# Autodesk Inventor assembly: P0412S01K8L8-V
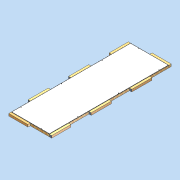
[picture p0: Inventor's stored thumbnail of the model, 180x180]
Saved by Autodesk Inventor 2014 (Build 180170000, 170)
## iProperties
Created: 2011-04
Part Number: P0412S01K8L8-V
Document SubType Name: Assembly
Designer: david.appleford
Description: 1w x 3w 01 Panel - 8 Locks 8 Lugs
Mass: 70000 g
Surface Area: 103979 cm^2
Volume: 351773 cm^3
Density: 0.198992 g/cm^3
Cost Center: £228.00
Justset: False
Title: 1w x 3w 01 Panel - 8 Locks 8 Lugs
Author: david.appleford
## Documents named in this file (4)
- C:\Documents and Settings\john.everitt\Local Settings\My Documents\Vault\Production MkII\VIRTUAL ELEMENTS\Virtual Walls\Virtual Timber + MgO\P0412S01K8L8-V.iam
- C:\Documents and Settings\john.everitt\Local Settings\My Documents\Vault\Production MkII\VIRTUAL ELEMENTS\Virtual Lugs\Superceded Lugs\LA02C3V.ipt
- C:\Documents and Settings\john.everitt\Local Settings\My Documents\Vault\Production MkII\VIRTUAL ELEMENTS\Virtual Lugs\Superceded Lugs\LA02M3V.ipt
- C:\Documents and Settings\john.everitt\Local Settings\My Documents\Vault\Production MkII\Virtual Elements\Virtual Walls\Virtual Timber + MgO\P0412S01K8-V.ipt
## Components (9 placed, 3 different names)
1. P0412S01K8-V:1 — Mate:1, Flush:1, Flush:2, Mate:2, Flush:3, Flush:4, Mate:3, Flush:5, Flush:6, Mate:4, Flush:7, Flush:8, Mate:5, Mate:6, Flush:9, Flush:10, Mate:7, Mate:8, Flush:11, Flush:12
2. LA02C3V:1 — Mate:1, Flush:1, Flush:2, Mate:9
3. LA02C3V:2 — Mate:2, Flush:3, Flush:4
4. LA02C3V:3 — Mate:4, Flush:7, Flush:8
5. LA02C3V:4 — Mate:3, Flush:5, Flush:6, Mate:11
6. LA02M3V:1 — Mate:6, Flush:9, Mate:11, Mate:12
7. LA02M3V:2 — Mate:5, Flush:10, Mate:12
8. LA02M3V:3 — Mate:8, Flush:12, Mate:10
9. LA02M3V:4 — Mate:7, Flush:11, Mate:9, Mate:10
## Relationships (24: Mate 12, Flush 12)
- Mate:1: P0412S01K8-V:1 ↔ LA02C3V:1
- Flush:1: P0412S01K8-V:1 ↔ LA02C3V:1
- Flush:2: P0412S01K8-V:1 ↔ LA02C3V:1
- Mate:2: P0412S01K8-V:1 ↔ LA02C3V:2
- Flush:3: P0412S01K8-V:1 ↔ LA02C3V:2
- Flush:4: P0412S01K8-V:1 ↔ LA02C3V:2
- Mate:3: P0412S01K8-V:1 ↔ LA02C3V:4
- Flush:5: P0412S01K8-V:1 ↔ LA02C3V:4
- Flush:6: P0412S01K8-V:1 ↔ LA02C3V:4
- Mate:4: P0412S01K8-V:1 ↔ LA02C3V:3
- Flush:7: P0412S01K8-V:1 ↔ LA02C3V:3
- Flush:8: P0412S01K8-V:1 ↔ LA02C3V:3
- Mate:5: P0412S01K8-V:1 ↔ LA02M3V:2
- Mate:6: P0412S01K8-V:1 ↔ LA02M3V:1
- Flush:9: P0412S01K8-V:1 ↔ LA02M3V:1
- Flush:10: P0412S01K8-V:1 ↔ LA02M3V:2
- Mate:7: P0412S01K8-V:1 ↔ LA02M3V:4
- Mate:8: P0412S01K8-V:1 ↔ LA02M3V:3
- Flush:11: P0412S01K8-V:1 ↔ LA02M3V:4
- Flush:12: P0412S01K8-V:1 ↔ LA02M3V:3
- Mate:9: LA02C3V:1 ↔ LA02M3V:4
- Mate:10: LA02M3V:3 ↔ LA02M3V:4
- Mate:11: LA02C3V:4 ↔ LA02M3V:1
- Mate:12: LA02M3V:1 ↔ LA02M3V:2
## Named parameters: t = 1 mm, Cl = 2 mm
